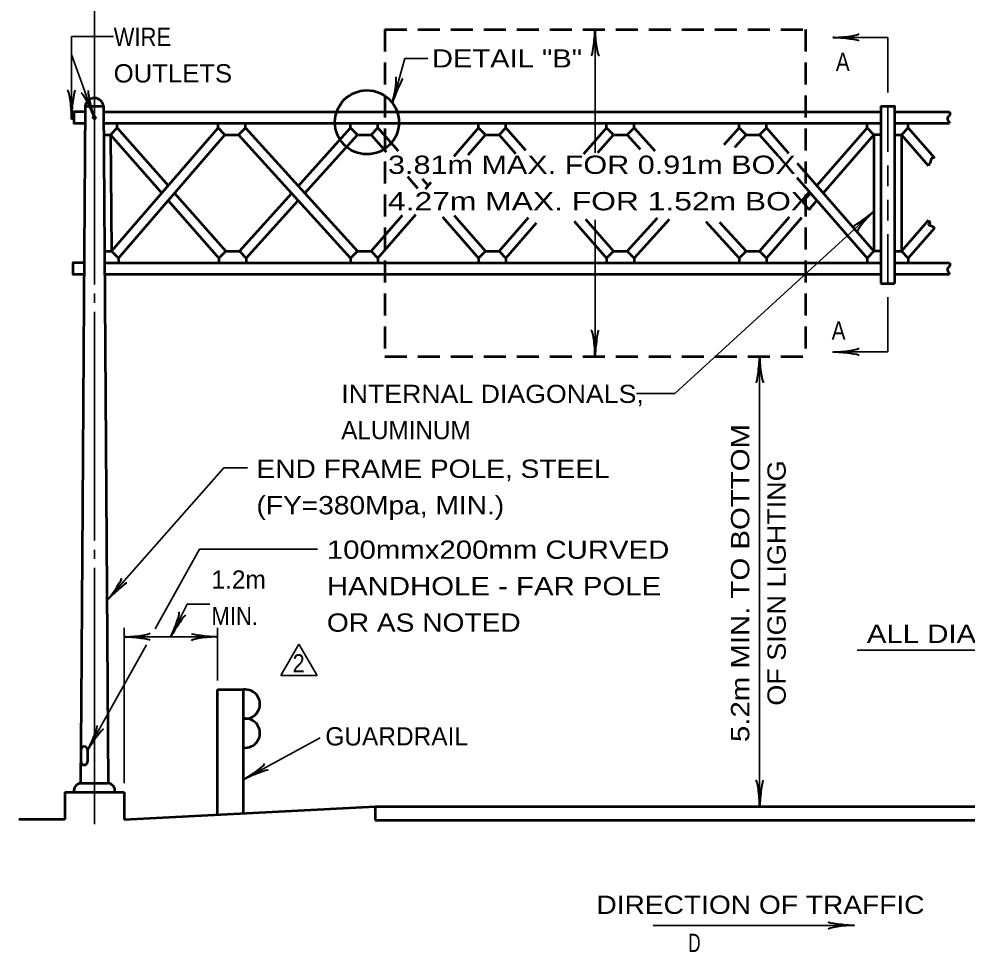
# Model space of a CAD drawing. Extents: x -29 to 827, y -14 to 530.
# Drawn here: x 171.4 to 296.8, y 336.4 to 459.8 of the extents above; entities that cross this region are included whole.
import ezdxf
from ezdxf.enums import TextEntityAlignment as Align

# ---------------------------------------------------------------- set-up
doc = ezdxf.new("R2010")
doc.units = 0
doc.header["$LTSCALE"] = 0.97
doc.linetypes.add('MEDIUM_DASHED', pattern=[4.5, 3, -1.5])
doc.layers.add('1', color=7, linetype='Continuous', lineweight=53)

msp = doc.modelspace()

# ---------------------------------------------------------------- linework, layer by layer
at = {"layer": '1', "lineweight": 35}
for p, q in [((181.3915, 424.6845), (181.3915, 463.8525)), ((247.6075, 458.4045), (247.6075, 442.1125)), ((178.3675, 446.9085), (178.3675, 457.4685)), ((178.3675, 457.4685), (183.9115, 457.4685)), ((286.3195, 457.3485), (279.0475, 457.3485)), ((286.3195, 450.0765), (286.3195, 457.3485)), ((178.3675, 455.0925), (181.2955, 446.8845)), ((286.3195, 448.2765), (286.3195, 442.2285)), ((286.3195, 440.4045), (286.3195, 437.6925)), ((286.3195, 435.8685), (286.3195, 433.1565)), ((247.6075, 433.2284), (247.6075, 415.1565)), ((286.3195, 431.3325), (286.3195, 424.8285)), ((181.3915, 422.2605), (181.3915, 423.4845)), ((286.3195, 423.0285), (286.3195, 415.7565)), ((181.3915, 390.8205), (181.3915, 421.0605)), ((269.3755, 415.1565), (269.3755, 355.6605)), ((286.3195, 415.7565), (279.0475, 415.7565)), ((181.3915, 388.3965), (181.3915, 389.5965)), ((189.4294, 379.1337), (195.3031, 389.6598)), ((195.3031, 389.6598), (210.897, 389.6598)), ((181.3915, 353.3085), (181.3915, 387.1965)), ((185.3035, 358.7565), (185.3035, 379.2859)), ((197.6648, 372.3018), (197.6648, 379.2859)), ((185.3035, 378.0859), (197.6648, 378.0859)), ((180.4854, 363.1054), (188.2599, 377.038)), ((208.4352, 377.1263), (206.0352, 372.9694)), ((208.4352, 377.1263), (210.8352, 372.9694)), ((282.2798, 376.3432), (374.2761, 376.3432)), ((210.8352, 372.9694), (206.0352, 372.9694)), ((201.1012, 359.2244), (211.2496, 364.7515)), ((255.2996, 339.9358), (281.9156, 339.9358))]:
    msp.add_line(p, q, dxfattribs=at)
at = {"layer": '1', "linetype": 'MEDIUM_DASHED'}
for p, q in [((219.7915, 458.4045), (219.7915, 415.1565)), ((219.7915, 458.4045), (275.4235, 458.4045)), ((275.4235, 458.4045), (275.4235, 415.1565)), ((219.7915, 415.1565), (275.4235, 415.1565))]:
    msp.add_line(p, q, dxfattribs=at)
at = {"layer": '1'}
for p, q in [((180.1675, 448.2765), (182.5915, 448.2765)), ((182.5915, 448.2765), (183.1915, 358.7565)), ((285.4075, 448.2765), (285.4075, 424.8285)), ((182.5915, 447.5085), (285.4075, 447.5085)), ((287.2315, 447.5085), (294.4795, 447.5085)), ((183.5275, 444.4845), (184.4155, 445.3965)), ((183.6475, 429.0765), (197.7355, 445.3965)), ((184.4155, 445.3965), (184.4155, 445.9965)), ((184.4155, 445.3965), (191.1355, 437.7645)), ((197.7355, 445.3965), (197.7355, 445.9965)), ((198.6475, 444.4845), (197.7355, 445.3965)), ((200.4475, 444.4845), (201.3595, 445.3965)), ((201.3595, 445.3965), (201.3595, 445.9965)), ((201.3595, 445.3965), (216.1675, 429.0765)), ((208.3435, 437.6925), (215.2555, 445.3965)), ((215.2555, 445.3965), (215.2555, 445.9965)), ((216.1675, 444.4845), (215.2555, 445.3965)), ((217.9915, 444.4845), (218.8795, 445.3965)), ((218.8795, 445.3965), (218.8795, 445.9965)), ((218.8795, 445.3965), (221.5496, 442.3422)), ((228.9549, 441.6696), (232.1995, 445.3965)), ((232.1995, 445.3965), (232.1995, 445.9965)), ((233.1115, 444.4845), (232.1995, 445.3965)), ((234.9115, 444.4845), (235.8235, 445.3965)), ((235.8235, 445.3965), (235.8235, 445.9965)), ((235.8235, 445.3965), (238.3993, 442.4378)), ((246.1111, 441.9428), (249.1195, 445.3965)), ((249.1195, 445.3965), (249.1195, 445.9965)), ((250.0315, 444.4845), (249.1195, 445.3965)), ((251.8555, 444.4845), (252.7675, 445.3965)), ((252.7675, 445.3965), (252.7675, 445.9965)), ((252.7675, 445.3965), (255.5183, 442.3601)), ((266.6635, 445.3965), (264.6387, 443.1649)), ((266.6635, 445.3965), (266.6635, 445.9965)), ((267.5755, 444.4845), (266.6635, 445.3965)), ((269.3755, 444.4845), (270.2875, 445.3965)), ((270.2875, 445.3965), (270.2875, 445.9965)), ((270.2875, 445.3965), (273.2071, 442.0429)), ((283.5835, 445.3965), (276.9355, 437.7645)), ((283.5835, 445.3965), (283.5835, 445.9965)), ((284.4955, 444.4845), (283.5835, 445.3965)), ((287.2315, 445.9965), (294.4795, 445.9965)), ((288.1195, 444.4845), (289.0315, 445.3965)), ((289.0315, 445.3965), (289.0315, 445.9965)), ((289.0315, 445.3965), (292.5115, 441.4125)), ((182.6155, 444.4845), (183.5275, 444.4845)), ((183.5275, 444.4845), (183.6475, 429.0765)), ((183.5275, 444.4845), (190.2955, 436.7805)), ((184.5595, 428.1645), (198.6475, 444.4845)), ((200.4475, 444.4845), (215.2555, 428.1645)), ((209.2075, 436.7565), (216.1675, 444.4845)), ((217.9915, 444.4845), (219.9722, 442.2057)), ((230.8106, 441.846), (233.1115, 444.4845)), ((234.9115, 444.4845), (237.0761, 441.9981)), ((247.9784, 442.1223), (250.0315, 444.4845)), ((251.8555, 444.4845), (253.5929, 442.568)), ((267.5755, 444.4845), (266.0568, 442.8107)), ((269.3755, 444.4845), (271.7619, 441.7434)), ((284.4955, 444.4845), (277.7995, 436.7805)), ((285.4075, 444.4845), (284.4955, 444.4845)), ((284.4955, 444.4845), (284.4955, 429.0765)), ((287.2315, 444.4845), (288.1195, 444.4845)), ((288.1195, 444.4845), (288.1195, 429.0765)), ((288.1195, 444.4845), (291.6715, 440.4285)), ((274.3415, 440.7398), (284.4955, 429.0765)), ((222.7775, 438.978), (224.142, 437.4081)), ((224.7599, 438.67), (225.5515, 437.7645)), ((225.1732, 437.3258), (225.9303, 438.1954)), ((274.3003, 438.8277), (283.5835, 428.1645)), ((191.9755, 436.7805), (198.7675, 429.0765)), ((200.5675, 429.0765), (207.4795, 436.7565)), ((276.0955, 436.7805), (275.1552, 435.7025)), ((191.1355, 435.7965), (197.8555, 428.1645)), ((201.4795, 428.1645), (208.3435, 435.7965)), ((276.9355, 435.7965), (275.9827, 434.7027)), ((218.8795, 428.1645), (223.8997, 433.9212)), ((217.9915, 429.0765), (222.1396, 433.8412)), ((227.432, 433.6376), (232.1995, 428.1645)), ((228.9788, 433.8143), (233.1115, 429.0765)), ((234.9115, 429.0765), (238.8026, 433.5373)), ((235.8235, 428.1645), (239.8752, 432.8159)), ((244.843, 433.0767), (249.1195, 428.1645)), ((246.348, 433.3076), (250.0315, 429.0765)), ((255.8199, 433.4457), (251.8555, 429.0765)), ((257.3946, 433.2641), (252.7675, 428.1645)), ((262.2508, 433.0185), (266.6635, 428.1645)), ((264.085, 432.9137), (267.5755, 429.0765)), ((273.3006, 433.5763), (269.3755, 429.0765)), ((274.9188, 433.4813), (270.2875, 428.1645)), ((291.6715, 433.1325), (288.1195, 429.0765)), ((292.5115, 432.1485), (289.0315, 428.1645)), ((182.7355, 429.0765), (183.6475, 429.0765)), ((183.6475, 429.0765), (184.5595, 428.1645)), ((198.7675, 429.0765), (197.8555, 428.1645)), ((198.7675, 429.0765), (200.5675, 429.0765)), ((200.5675, 429.0765), (201.4795, 428.1645)), ((216.1675, 429.0765), (215.2555, 428.1645)), ((216.1675, 429.0765), (217.9915, 429.0765)), ((217.9915, 429.0765), (218.8795, 428.1645)), ((233.1115, 429.0765), (232.1995, 428.1645)), ((233.1115, 429.0765), (234.9115, 429.0765)), ((234.9115, 429.0765), (235.8235, 428.1645)), ((250.0315, 429.0765), (249.1195, 428.1645)), ((250.0315, 429.0765), (251.8555, 429.0765)), ((251.8555, 429.0765), (252.7675, 428.1645)), ((267.5755, 429.0765), (266.6635, 428.1645)), ((267.5755, 429.0765), (269.3755, 429.0765)), ((269.3755, 429.0765), (270.2875, 428.1645)), ((284.4955, 429.0765), (283.5835, 428.1645)), ((285.4075, 429.0765), (284.4955, 429.0765)), ((287.2315, 429.0765), (288.1195, 429.0765)), ((288.1195, 429.0765), (289.0315, 428.1645)), ((184.5595, 428.1645), (184.5595, 427.5645)), ((197.8555, 428.1645), (197.8555, 427.5645)), ((201.4795, 428.1645), (201.4795, 427.5645)), ((215.2555, 428.1645), (215.2555, 427.5645)), ((218.8795, 428.1645), (218.8795, 427.5645)), ((232.1995, 428.1645), (232.1995, 427.5645)), ((235.8235, 428.1645), (235.8235, 427.5645)), ((249.1195, 428.1645), (249.1195, 427.5645)), ((252.7675, 428.1645), (252.7675, 427.5645)), ((266.6635, 428.1645), (266.6635, 427.5645)), ((270.2875, 428.1645), (270.2875, 427.5645)), ((283.5835, 428.1645), (283.5835, 427.5645)), ((289.0315, 428.1645), (289.0315, 427.5645)), ((287.2315, 427.5645), (294.4795, 427.5645)), ((182.7355, 426.0525), (285.4075, 426.0525)), ((287.2315, 426.0525), (294.4795, 426.0525)), ((285.4075, 424.8285), (287.2315, 424.8285)), ((197.6648, 354.602), (197.6648, 371.1018)), ((197.6648, 371.1018), (201.1011, 371.1018)), ((201.1011, 354.602), (201.1011, 371.1018)), ((180.4854, 363.1054), (180.4854, 361.5934)), ((177.4555, 357.5565), (185.3035, 357.5565)), ((177.4555, 357.5565), (177.4555, 353.9325)), ((185.3035, 357.5565), (185.3035, 353.9325)), ((218.5435, 355.6605), (218.5435, 353.8605)), ((177.4555, 353.9325), (171.4075, 353.9325)), ((218.5435, 353.8605), (375.7915, 353.8605))]:
    msp.add_line(p, q, dxfattribs=at)
at = {"layer": '1', "lineweight": 35}
for points in [[(220.7997, 448.6987), (222.4614, 454.5721), (225.4941, 454.5721)], [(284.4955, 434.3383), (258.1482, 410.2744), (253.0878, 410.2744)], [(183.0235, 382.9005), (198.5115, 400.4305), (201.627, 400.4305)], [(191.4842, 378.0859), (193.659, 382.4043), (196.6471, 382.4043)]]:
    msp.add_lwpolyline(points, dxfattribs=at)
at = {"layer": '1'}
for points in [[(180.1675, 448.2765), (179.9995, 422.5725), (179.8075, 395.3565), (179.6395, 369.3405)], [(285.4075, 448.2765), (287.2315, 448.2765), (287.2315, 424.8285)], [(178.6555, 446.9085), (178.3675, 446.9085), (178.3675, 446.6205), (178.6555, 446.6205)], [(180.1675, 447.5085), (178.6555, 447.5085), (178.6555, 445.9965), (180.1675, 445.9965)], [(182.6155, 445.9965), (184.4155, 445.9965), (232.1995, 445.9965)], [(232.1995, 445.9965), (235.8235, 445.9965), (283.5835, 445.9965), (285.4075, 445.9965)], [(198.6475, 444.4845), (199.5355, 444.4845), (200.4475, 444.4845)], [(216.1675, 444.4845), (217.0795, 444.4845), (217.9915, 444.4845)], [(233.1115, 444.4845), (233.9995, 444.4845), (234.9115, 444.4845)], [(250.0315, 444.4845), (250.9435, 444.4845), (251.8555, 444.4845)], [(267.5755, 444.4845), (268.4635, 444.4845), (269.3755, 444.4845)], [(180.0235, 427.5645), (178.5355, 427.5645), (178.5355, 426.0525), (180.0235, 426.0525)], [(182.7355, 427.5645), (184.5595, 427.5645), (232.1995, 427.5645)], [(232.1995, 427.5645), (235.8235, 427.5645), (283.5835, 427.5645), (285.4075, 427.5645)], [(179.6395, 369.3405), (179.5675, 358.7565), (183.1915, 358.7565)], [(185.3035, 353.9325), (218.5435, 355.6605), (375.7915, 355.6605)]]:
    msp.add_lwpolyline(points, dxfattribs=at)
for centre, radius in [((217.4295, 446.1365), 4.2336), ((181.3837, 446.7611), 0.1512)]:
    msp.add_circle(centre, radius, dxfattribs=at)
for centre, radius, start, end in [((181.3837, 448.1113), 1.2204, 7.62224, 172.37776), ((201.3458, 369.1866), 1.9308, 262.71824, 97.28176), ((201.3458, 365.3561), 1.9308, 262.71824, 97.28176), ((180.0342, 363.113), 0.4536, 0, 180), ((180.0342, 361.601), 0.4536, 180, 0), ((179.75, 357.6822), 1.0956, 99.49518, 186.76502), ((183.0174, 357.6822), 1.0956, 353.23498, 80.50482)]:
    msp.add_arc(centre, radius, start, end, dxfattribs=at)
at = {"layer": '1', "lineweight": 40}
for centre, major_axis, ratio, start_param, end_param in [((247.3533, 457.0482), (0.2125, 2.1246), 0.07063, 3.14071475, 5.41810995), ((247.9435, 457.0836), (-0.1889, 2.16), 0.122415, 0.89635335, 3.14159265), ((280.3788, 457.6793), (-2.16, -0.1889), 0.122415, 0.89635335, 3.14159265), ((280.4142, 457.0892), (-2.1246, 0.2125), 0.07063, 3.14071475, 5.41810995), ((220.8371, 450.0489), (-0.4031, -2.1129), 0.122415, 0.89635335, 3.14159265), ((221.4101, 449.9234), (0.7766, 1.9708), 0.07063, 6.28230741, 8.55970261), ((178.0258, 448.2323), (0.1884, -2.16), 0.122415, 0.89635335, 3.14159265), ((178.0258, 448.2323), (0.1884, -2.16), 0.122415, 0.89635335, 3.14159265), ((178.6159, 448.2676), (0.2129, 2.1246), 0.07063, 6.28230741, 8.55970261), ((178.6159, 448.2676), (0.2129, 2.1246), 0.07063, 6.28230741, 8.55970261), ((181.0835, 448.2492), (-0.5171, 2.0716), 0.07063, 6.28230741, 8.55970261), ((180.5399, 448.0167), (0.9069, -1.9695), 0.122415, 0.89635335, 3.14159265), ((283.3314, 433.619), (-1.6985, -1.2658), 0.07063, 6.28230741, 8.55970261), ((283.7522, 433.2104), (1.4559, 1.5835), 0.122415, 0.89635335, 3.14159265), ((247.2751, 416.4802), (0.1889, -2.16), 0.122415, 0.89635335, 3.14159265), ((247.8652, 416.5157), (-0.2125, -2.1246), 0.07063, 3.14071475, 5.41810995), ((269.1261, 413.805), (0.2125, 2.1246), 0.07063, 3.14071475, 5.41810995), ((269.7163, 413.8404), (-0.1889, 2.16), 0.122415, 0.89635335, 3.14159265), ((280.4142, 415.5092), (-2.1246, 0.2125), 0.07063, 3.14071475, 5.41810995), ((280.3788, 416.0993), (-2.16, -0.1889), 0.122415, 0.89635335, 3.14159265), ((183.6577, 384.1186), (-1.2875, -1.7446), 0.122415, 0.89635335, 3.14159265), ((184.1237, 383.7547), (-1.5651, -1.4525), 0.07063, 3.14071475, 5.41810995), ((191.777, 379.4045), (-0.7965, -1.9981), 0.122415, 0.89635335, 3.14159265), ((192.3158, 379.1726), (-1.1363, -1.7877), 0.07063, 3.14071475, 5.41810995), ((186.6481, 377.832), (-2.1077, 0.2108), 0.07063, 3.14071475, 5.41810995), ((186.6481, 377.832), (-2.1077, 0.2108), 0.07063, 3.14071475, 5.41810995), ((186.6129, 378.4175), (-2.1428, -0.1874), 0.122415, 0.89635335, 3.14159265), ((186.6129, 378.4175), (-2.1428, -0.1874), 0.122415, 0.89635335, 3.14159265), ((196.3554, 377.7543), (2.1428, 0.1874), 0.122415, 0.89635335, 3.14159265), ((196.3202, 378.3398), (2.1077, -0.2108), 0.07063, 3.14071475, 5.41810995), ((180.8339, 364.4104), (-0.8805, -1.9625), 0.122415, 0.89635335, 3.14159265), ((181.3623, 364.1558), (-1.2111, -1.7379), 0.07063, 3.14071475, 5.41810995), ((202.0926, 360.1419), (-1.7922, -1.1895), 0.122415, 0.89635335, 3.14159265), ((202.4035, 359.6445), (-1.9518, -0.823), 0.07063, 3.14071475, 5.41810995), ((269.0479, 356.9852), (0.1889, -2.16), 0.122415, 0.89635335, 3.14159265), ((269.638, 357.0206), (-0.2125, -2.1246), 0.07063, 3.14071475, 5.41810995), ((280.5885, 339.5967), (2.16, 0.1889), 0.122415, 0.89635335, 3.14159265), ((280.553, 340.1868), (2.1246, -0.2125), 0.07063, 3.14071475, 5.41810995)]:
    msp.add_ellipse(centre, major_axis=major_axis, ratio=ratio, start_param=start_param, end_param=end_param, dxfattribs=at)
at = {"layer": '1'}
for points in [[(294.4795, 447.5085), (294.5515, 447.2205), (294.3355, 446.8845), (294.2155, 446.5245), (294.4075, 446.1885), (294.4795, 445.9965)], [(292.5115, 441.4125), (292.1275, 441.3645), (291.9595, 440.8605), (291.6715, 440.4285)], [(291.6715, 433.1325), (291.9115, 432.8685), (291.7195, 432.6045), (292.0795, 432.4605), (292.5115, 432.1485)], [(294.4795, 427.5645), (294.5515, 427.2765), (294.3355, 426.9405), (294.2155, 426.5805), (294.4075, 426.2445), (294.4795, 426.0525)]]:
    msp.add_spline(points, degree=3, dxfattribs=at)

# ---------------------------------------------------------------- texts
for s, height, width, p in [('WIRE', 2.419, 0.9, (183.9355, 456.2205)), ('DETAIL "B"', 2.4, 1.2, (226.0356, 453.3803)), ('A', 2.419, 0.85, (279.4555, 452.9085)), ('OUTLETS', 2.419, 1.05, (183.9355, 451.3965)), ('3.81m MAX. FOR 0.91m BOX', 2.419, 1.25, (220.2215, 439.3058)), ('4.27m MAX. FOR 1.52m BOX', 2.419, 1.3, (220.2215, 434.4866)), ('A', 2.419, 0.85, (278.9035, 417.3885)), ('INTERNAL DIAGONALS,', 2.4, 1.1, (214.0368, 409.0205)), ('END FRAME POLE, STEEL', 2.419, 1.15, (202.822, 399.1056)), ('(FY=380Mpa, MIN.)', 2.419, 1.15, (202.822, 394.2864)), ('100mmx200mm CURVED', 2.419, 1.2, (212.1358, 388.4047)), ('HANDHOLE - FAR POLE', 2.419, 1.2, (212.1358, 383.5855)), ('MIN.', 2.419, 0.9, (196.8705, 379.6342)), ('OR AS NOTED', 2.419, 1.15, (212.1358, 378.7663)), ('2', 2.4, 0.9, (207.594, 373.3897)), ('DIRECTION OF TRAFFIC', 2.419, 1.15, (247.7876, 341.4478)), ('D', 2.419, 0.7, (259.9286, 336.4049))]:
    msp.add_text(s, height=height, dxfattribs=dict(at, width=width)).set_placement(p)
for s, height, p in [('ALUMINUM', 2.4, (214.0368, 404.2205)), ('1.2m', 2.419, (196.8705, 384.4534)), ('GUARDRAIL', 2.419, (211.9302, 363.7201))]:
    msp.add_text(s, height=height, dxfattribs=at).set_placement(p)
for s, width, p in [('5.2m MIN. TO BOTTOM', 1.2, (268.0075, 385.2045)), ('OF SIGN LIGHTING', 1.1, (272.8267, 385.2046))]:
    msp.add_text(s, height=2.419, rotation=90, dxfattribs=dict(at, width=width)).set_placement(p, align=Align.CENTER)
at = {"layer": '1', "width": 1.2}
msp.add_text('ALL DIAGONAL BRACES TO BE AT NOMINAL 45', height=2.419, dxfattribs=at).set_placement((327.5638, 377.2728), align=Align.CENTER)

doc.saveas('drawing.dxf')
